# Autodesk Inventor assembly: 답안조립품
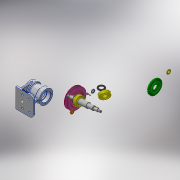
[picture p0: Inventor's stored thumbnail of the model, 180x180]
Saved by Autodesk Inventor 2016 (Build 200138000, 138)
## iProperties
Created: 2020-06
Part Number: 답안조립품
Material: 일반
Document SubType Name: Assembly
Designer: woori
Author: woori
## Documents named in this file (12)
- C:\Users\woori\Desktop\700606V1048\답안조립품.iam
- C:\Users\woori\Desktop\700606V1048\본체.ipt
- C:\Users\woori\Desktop\700606V1048\V-벨트풀리.ipt
- C:\Users\woori\Desktop\700606V1048\너트 M10.ipt
- C:\Users\woori\Desktop\700606V1048\베어링 6204.ipt
- C:\Users\woori\Desktop\700606V1048\볼트 M4.ipt
- C:\Users\woori\Desktop\700606V1048\스프링 와셔 10.ipt
- C:\Users\woori\Desktop\700606V1048\오일 실 20 32 5.ipt
- C:\Users\woori\Desktop\700606V1048\축.ipt
- C:\Users\woori\Desktop\700606V1048\커버.ipt
- C:\Users\woori\Desktop\700606V1048\키 5x5x12.ipt
- C:\Users\woori\Desktop\700606V1048\평면 와셔 10x21.ipt
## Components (1 placed, 1 different names)
1. V-벨트풀리:1
